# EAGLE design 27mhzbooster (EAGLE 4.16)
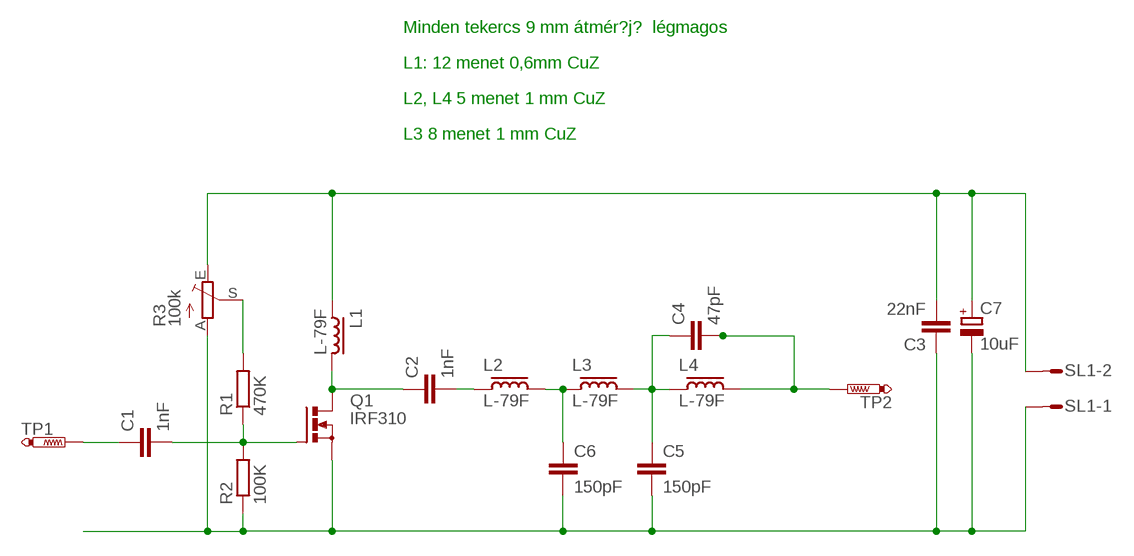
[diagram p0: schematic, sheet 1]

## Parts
C1  1nF  C7.5/3  [C7.5B3]
C2  1nF  C7.5/3  [C7.5B3]
C3  22nF  C7.5/3  [C7.5B3]
C4  47pF  C7.5/3  [C7.5B3]
C5  150pF  C7.5/3  [C7.5B3]
C6  150pF  C7.5/3  [C7.5B3]
C7  10uF  CPOL-EUE5-6  [E5-6]
L1  L-79F  [79F]
L2  L-79F  [79F]
L3  L-79F  [79F]
L4  L-79F  [79F]
Q1  IRF310  IRF512  [TO220BV]
R1  470K  R-EU_0207/7  [0207/7]
R2  100K  R-EU_0207/7  [0207/7]
R3  100k  TRIM_EU-CA6V  [CA6V]
SL1  M02S  [02P]
TP1  PTR1PAD1-13  [P1-13]
TP2  PTR1PAD1-13  [P1-13]

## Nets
+12V: C3.2 C7.+ L1.1 R3.E SL1.2
GND: C3.1 C5.2 C6.2 C7.- Q1.S R2.1 R3.A SL1.1
N$1: C1.1 TP1.1(TP)
N$2: C1.2 Q1.G R1.1 R2.2
N$3: C4.2 L4.2 TP2.1(TP)
N$4: C2.1 L1.2 Q1.D
N$5: C4.1 C5.1 L3.2 L4.1
N$6: C2.2 L2.1
N$7: C6.1 L2.2 L3.1
N$8: R1.2 R3.S

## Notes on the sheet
- Minden tekercs 9 mm átmér?j?  légmagos
- L1: 12 menet 0,6mm CuZ
- L2, L4 5 menet 1 mm CuZ
- L3 8 menet 1 mm CuZ

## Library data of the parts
C1-C6 = capacitor-wima:C: CAPACITOR
C7 = rcl-2:CPOL-EU: POLARIZED CAPACITOR, European symbol
L1-L4 = inductors-jwmiller:L: INDUCTORS
Q1 = transistor-power:IRF512: N-CHANNEL MOS FET
R1 R2 = rcl:R-EU_: RESISTOR, European symbol
R3 = pot:TRIM_EU-: POTENTIOMETER
SL1 = con-amp-quick:M02S: AMP QUICK CONNECTOR
TP1 TP2 = testpad:PTR1: TEST PIN

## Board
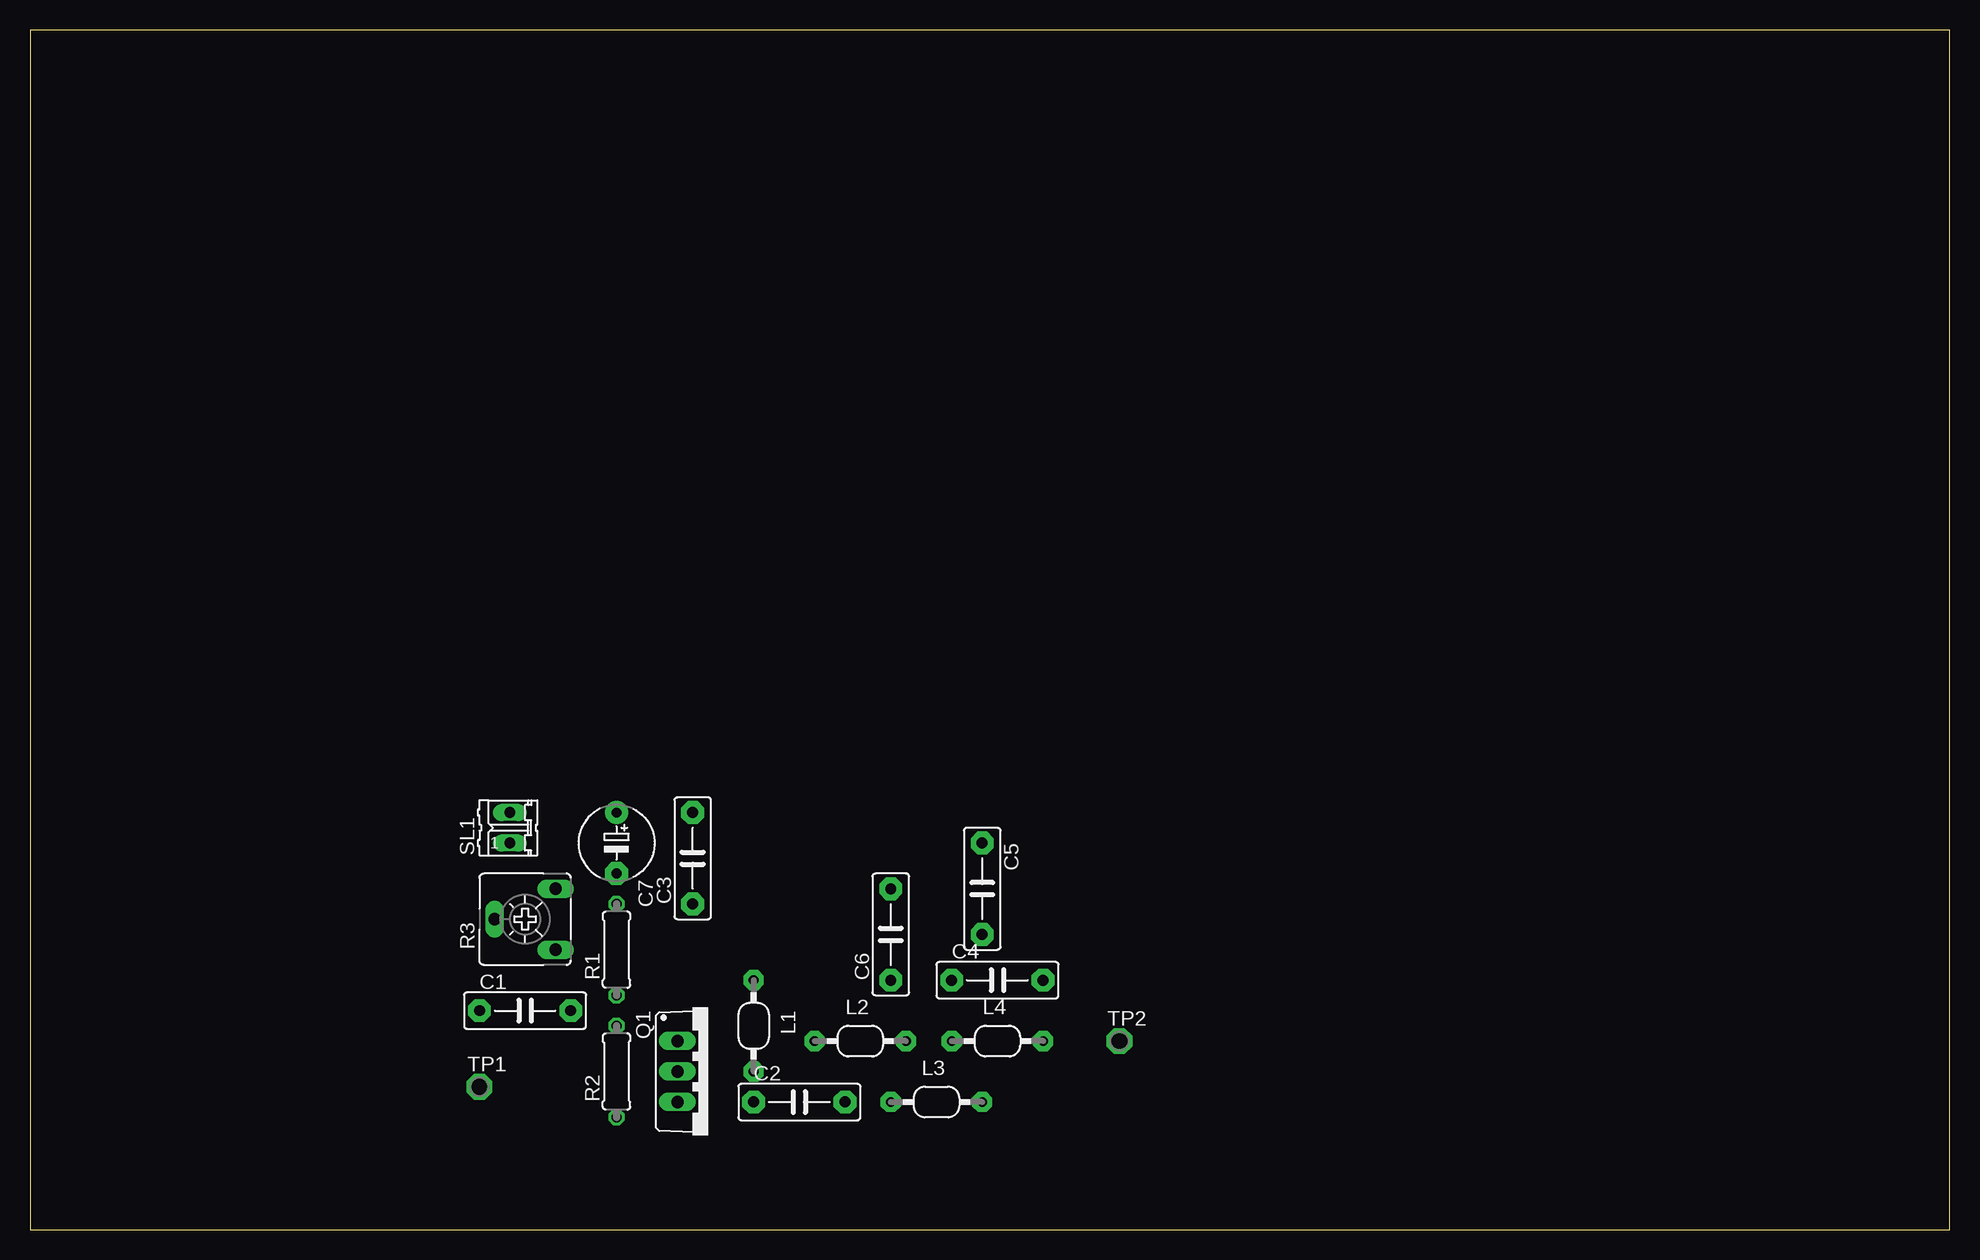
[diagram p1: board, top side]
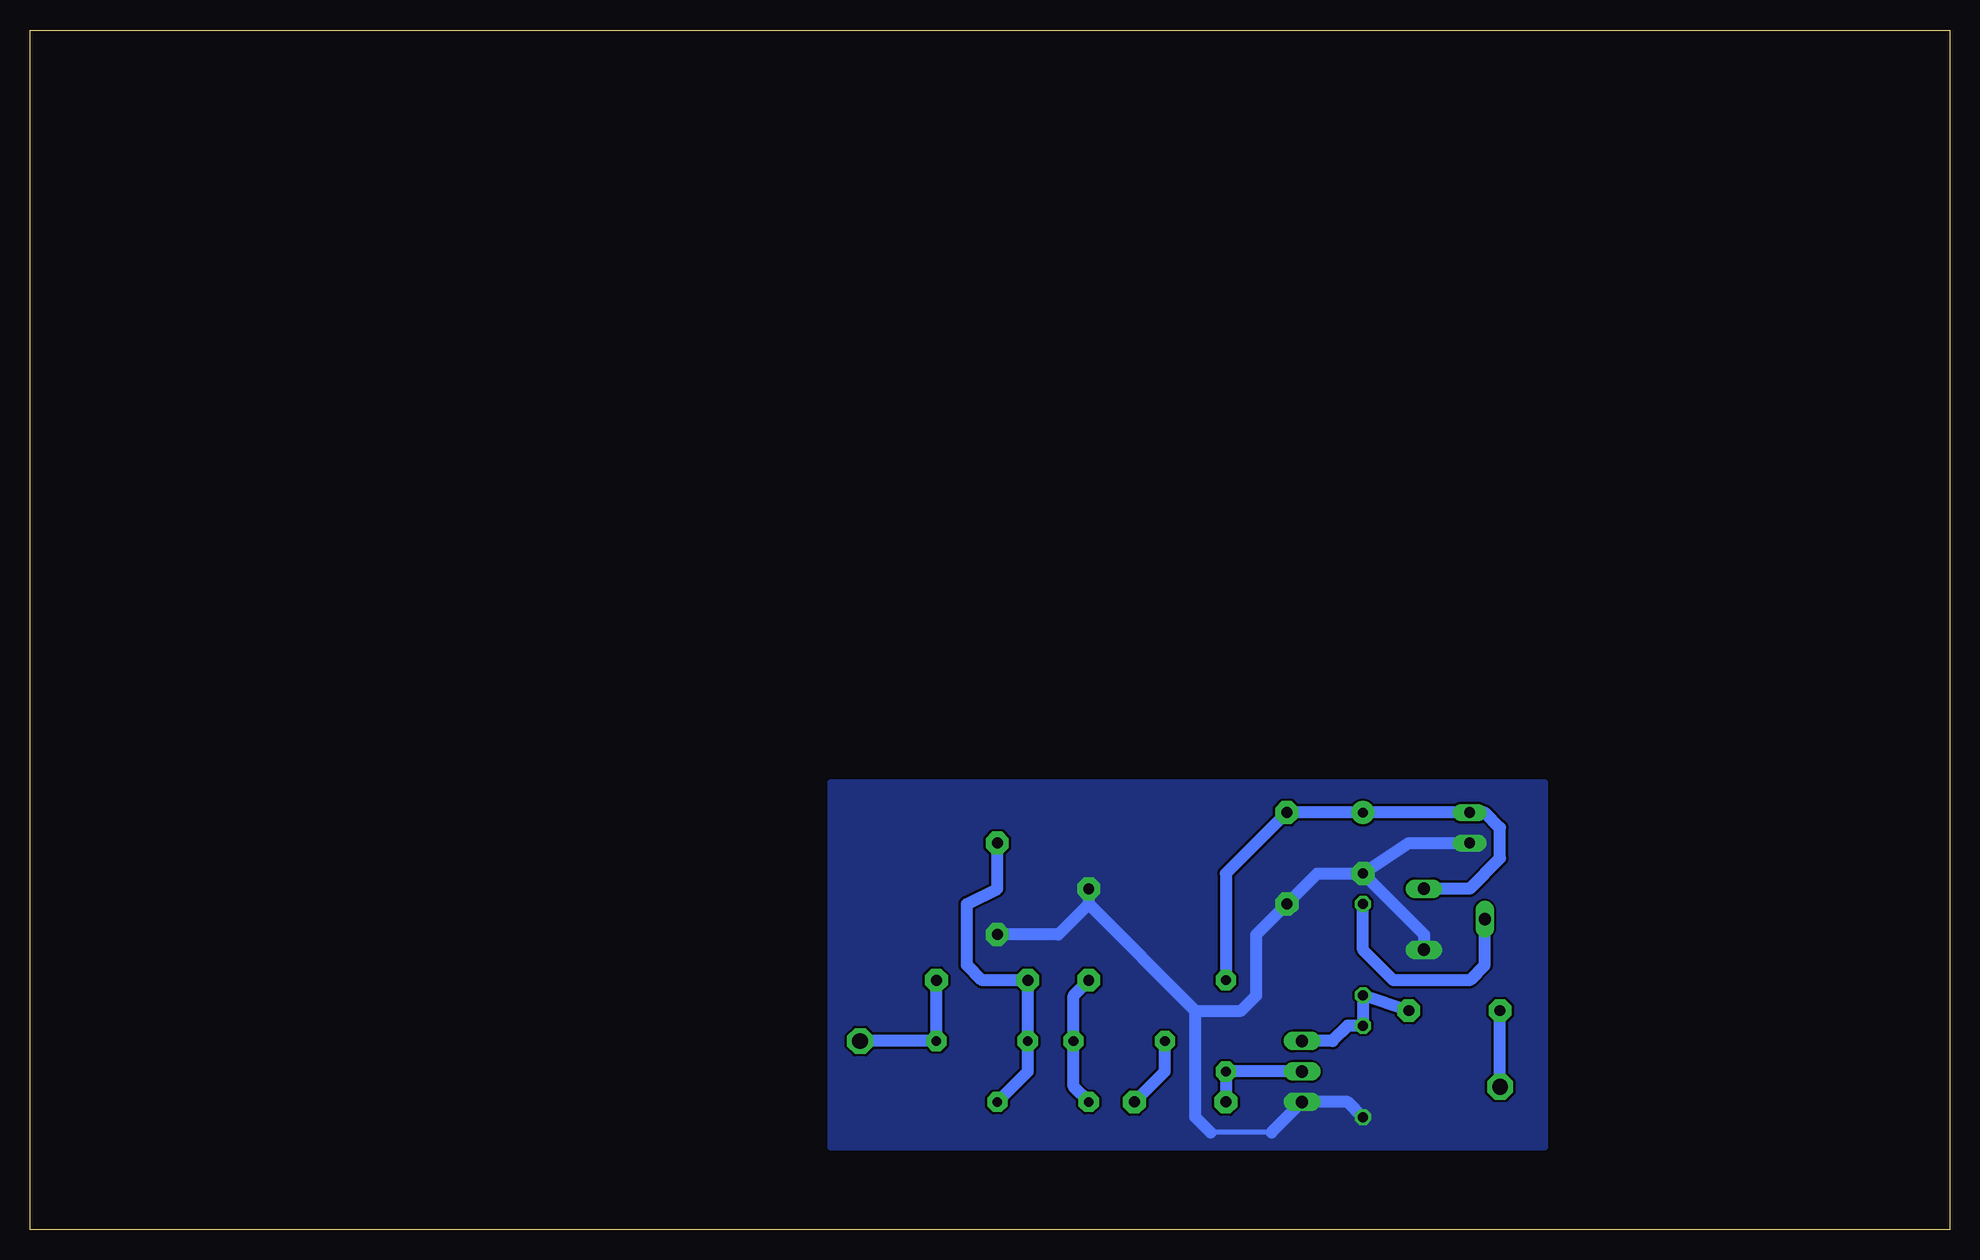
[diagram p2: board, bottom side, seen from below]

Size 160 x 100 mm. Coordinates in mm from the lower left corner, seen from the top.
Outline: 0,0 160,0 160,100 0,100 0,0
Copper layers (1*16): Top 0.035mm / dielectric 1.5mm / Bottom 0.035mm
Design rules "default": minimum track width 10mil, minimum drill 24mil, track to track 8mil, track to pad 8mil, pad to pad 8mil, via to via 8mil, smd to smd 8mil, copper to edge 40mil, drill to drill 8mil, minimum pad ring 10mil, minimum via ring 8mil, stop-mask expansion 4mil, vias tented up to drill 0mil, thermal gap 10mil

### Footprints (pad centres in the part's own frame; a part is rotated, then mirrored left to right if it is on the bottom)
C7.5B3 = drill 0.914 pad 1.905 octagon: 1 -3.81,0; 2 3.81,0
E5-6 = drill 0.813 pad 1.905 round: + -2.54,0 | drill 0.813 pad 1.905 octagon: - 2.54,0
79F = drill 0.813 pad 1.676 octagon: 1 -3.81,0; 2 3.81,0
TO220BV = drill 1.016 long: D 0,-2.54; G -2.54,-2.54; S 2.54,-2.54
0207/7 = drill 0.813 octagon: 1 -3.81,0; 2 3.81,0
CA6V = drill 1.016 long: A -2.54,-2.54; E 2.54,-2.54; S 0,2.54
02P = drill 0.914 long: 1 -1.27,0; 2 1.27,0
P1-13 = drill 1.321 pad 2.159 octagon: 1 0,0

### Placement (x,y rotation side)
C1  41.27,18.25 0 top
C2  64.13,10.63 0 top
C3  55.24,30.95 90 top
C4  80.64,20.79 0 top
C5  79.37,28.41 270 top
C6  71.75,24.6 90 top
C7  48.89,32.22 270 top
L1  60.32,16.98 270 top
L2  69.21,15.71 0 top
L3  75.56,10.63 0 top
L4  80.64,15.71 0 top
Q1  56.51,13.17 270 top
R1  48.89,23.33 90 top
R2  48.89,13.17 90 top
R3  41.27,25.87 90 top
SL1  40,33.49 90 top
TP1  37.46,11.9 0 top
TP2  90.8,15.71 0 top

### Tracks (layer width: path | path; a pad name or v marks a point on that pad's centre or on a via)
+12V
  Bottom 1.016: L1.1 60.32,29.68 C3.2 C7.+ SL1.2 38.73,34.76 37.46,33.49 37.46,30.95 40,28.41 R3.E
GND
  Bottom 0.406: 56.51,8.09 61.59,8.09
  Bottom 1.016: R3.A 43.81,24.6 C7.- | C7.- 45.08,32.22 SL1.1 | C7.- 52.7,29.68 C3.1 57.78,24.6 57.78,19.52 59.05,18.25 62.86,18.25 | 71.75,27.14 C6.2 | 62.86,18.25 71.75,27.14 | R2.1 50.16,10.63 Q1.S 56.51,8.09 | C5.2 74.29,24.6 71.75,27.14 | 61.59,8.09 62.86,9.36 62.86,18.25
  pour Bottom (no thermals): 33.65,37.3 93.34,37.3 93.34,6.82 33.65,6.82
N$1
  Bottom 1.016: TP1.1 C1.1
N$2
  Bottom 1.016: C1.2 R1.1 R2.2 50.16,16.98 51.43,15.71 Q1.G
N$3
  Bottom 1.016: C4.2 L4.2 TP2.1
N$4
  Bottom 1.016: L1.2 Q1.D L1.2 | L1.2 C2.1
N$5
  Bottom 1.016: C5.1 79.37,28.41 81.91,27.14 81.91,22.06 80.64,20.79 C4.1 L4.1 76.83,13.17 L3.2
N$6
  Bottom 1.016: L2.1 65.4,13.17 C2.2
N$7
  Bottom 1.016: L3.1 73.02,11.9 L2.2 73.02,19.52 C6.1
N$8
  Bottom 1.016: R1.2 48.89,23.33 46.35,20.79 40,20.79 38.73,22.06 R3.S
